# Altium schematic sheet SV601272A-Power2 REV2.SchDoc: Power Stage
size 431 x 279 mm; Date: Not shown in title block; ApprovedBy: Not shown in title block; CheckedBy: Not shown in title block; Author: Not shown in title block; CompanyName: Not shown in title block; Engineer: Not shown in title block; Organization: Not shown in title block; Address1: Not shown in title block; Address2: Not shown in title block; Address3: Not shown in title block; Address4: Not shown in title block; DocumentNumber: 5; Revision: Use project parameter SCH_Rev; SheetNumber: 5; SheetTotal: 11; PageSetup: Record=PageOptions¦CenterHorizontal=True¦CenterVertical=True¦PrintScale=0.62¦XCorrection=1.00¦YCorrection=1.00¦PrintKind=0¦BorderSize=5000000¦LeftOffset=0¦BottomOffset=0¦Orientation=2¦PaperLength=1000¦PaperWidth=1000¦Scale=100¦PaperSource=15¦PrintQuality=600¦MediaType=1¦DitherType=10¦PrintScaleMode=1¦PaperKind=Letter (8.5 x 11")¦PaperIndex=1
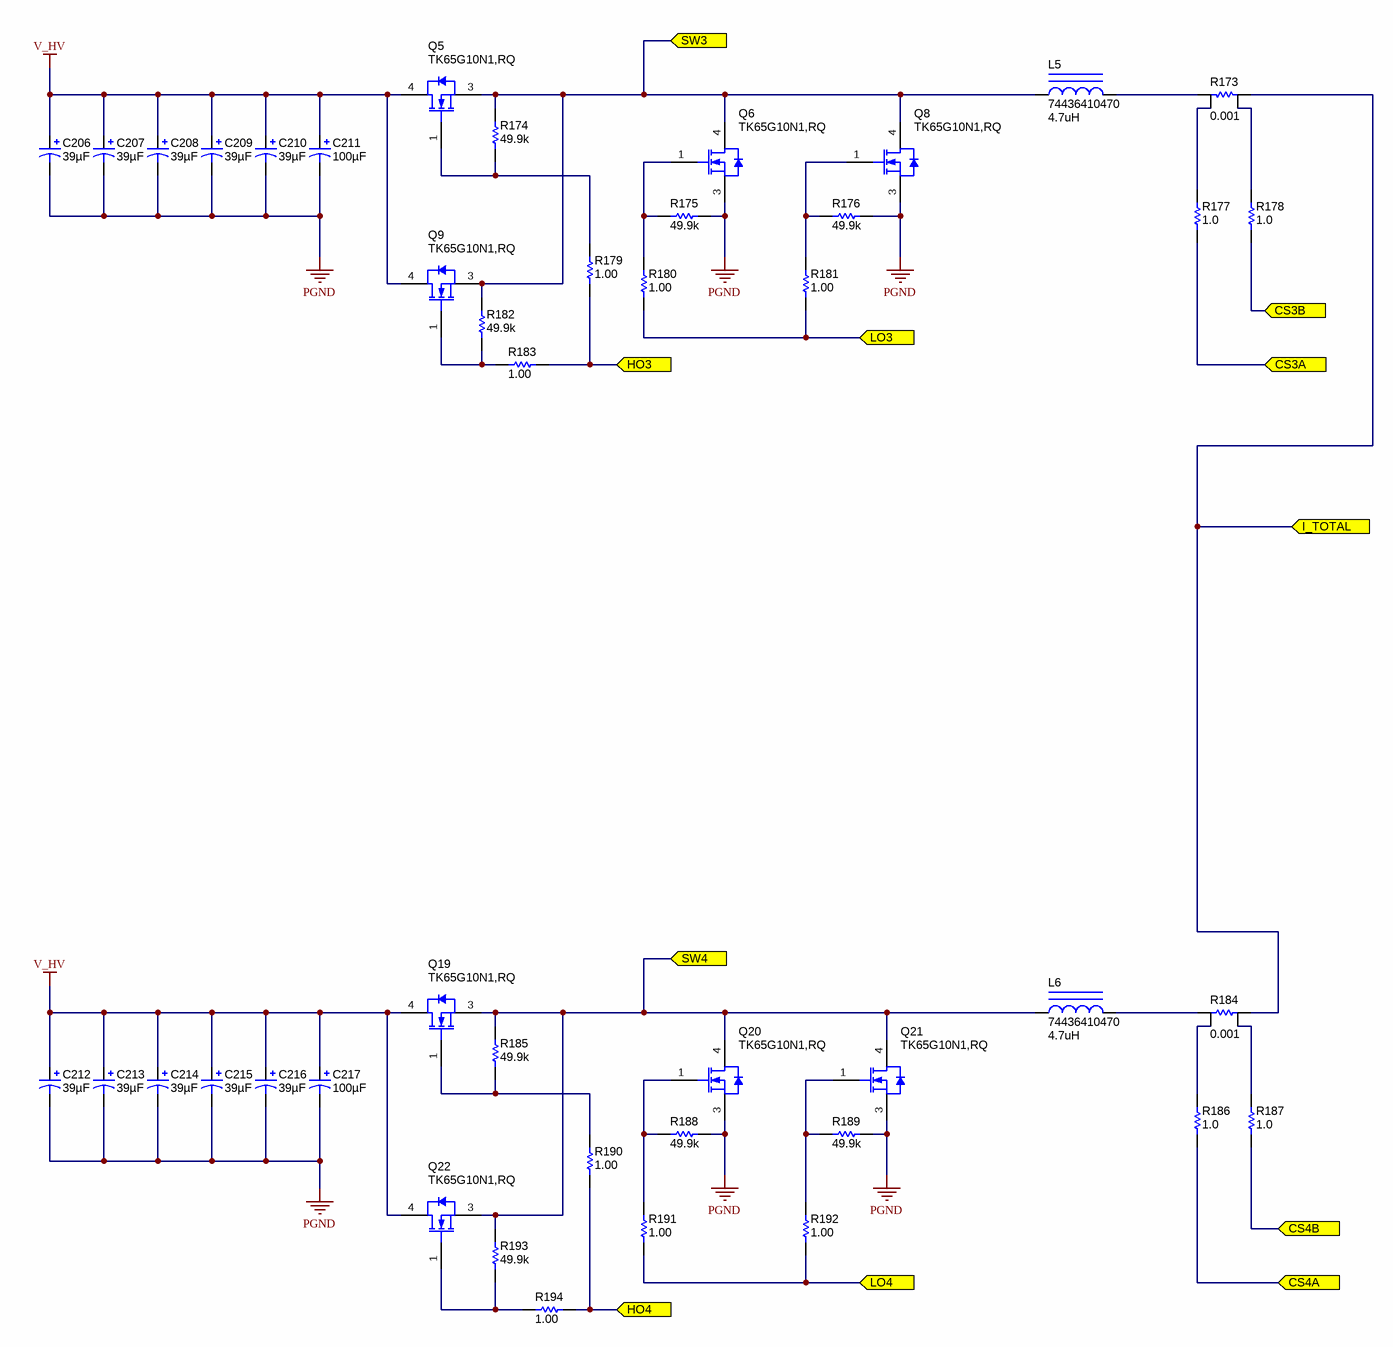
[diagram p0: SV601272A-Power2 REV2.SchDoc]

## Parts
C206  ValueDisplayed: 39µF  [HXA_JA0]  (hidden comment: HHXA800ARA390MJA0G)
C207  ValueDisplayed: 39µF  [HXA_JA0]  (hidden comment: HHXA800ARA390MJA0G)
C208  ValueDisplayed: 39µF  [HXA_JA0]  (hidden comment: HHXA800ARA390MJA0G)
C209  ValueDisplayed: 39µF  [HXA_JA0]  (hidden comment: HHXA800ARA390MJA0G)
C210  ValueDisplayed: 39µF  [HXA_JA0]  (hidden comment: HHXA800ARA390MJA0G)
C211  ValueDisplayed: 100µF  [CAPSMT_62_LH0]  (hidden comment: EMVH101GDA101MLH0S)
C212  ValueDisplayed: 39µF  [HXA_JA0]  (hidden comment: HHXA800ARA390MJA0G)
C213  ValueDisplayed: 39µF  [HXA_JA0]  (hidden comment: HHXA800ARA390MJA0G)
C214  ValueDisplayed: 39µF  [HXA_JA0]  (hidden comment: HHXA800ARA390MJA0G)
C215  ValueDisplayed: 39µF  [HXA_JA0]  (hidden comment: HHXA800ARA390MJA0G)
C216  ValueDisplayed: 39µF  [HXA_JA0]  (hidden comment: HHXA800ARA390MJA0G)
C217  ValueDisplayed: 100µF  [CAPSMT_62_LH0]  (hidden comment: EMVH101GDA101MLH0S)
L5  74436410470  value 4.7uH  [WE-HCF_2818]
L6  74436410470  value 4.7uH  [WE-HCF_2818]
Q5  TK65G10N1,RQ  [DDPAK]
Q6  TK65G10N1,RQ  [DDPAK]
Q8  TK65G10N1,RQ  [DDPAK]
Q9  TK65G10N1,RQ  [DDPAK]
Q19  TK65G10N1,RQ  [DDPAK]
Q20  TK65G10N1,RQ  [DDPAK]
Q21  TK65G10N1,RQ  [DDPAK]
Q22  TK65G10N1,RQ  [DDPAK]
R173  ValueDisplayed: 0.001  [RES_WSL2726]  (hidden comment: WSL27261L000FEB)
R174  ValueDisplayed: 49.9k  [0805_HV]  (hidden comment: CRCW080549K9FKEA)
R175  ValueDisplayed: 49.9k  [0805_HV]  (hidden comment: CRCW080549K9FKEA)
R176  ValueDisplayed: 49.9k  [0805_HV]  (hidden comment: CRCW080549K9FKEA)
R177  ValueDisplayed: 1.0  [0603L]  (hidden comment: CRCW06031R00JNEA)
R178  ValueDisplayed: 1.0  [0603L]  (hidden comment: CRCW06031R00JNEA)
R179  ValueDisplayed: 1.00  [0805_HV]  (hidden comment: CRCW08051R00FKEA)
R180  ValueDisplayed: 1.00  [0805_HV]  (hidden comment: CRCW08051R00FKEA)
R181  ValueDisplayed: 1.00  [0805_HV]  (hidden comment: CRCW08051R00FKEA)
R182  ValueDisplayed: 49.9k  [0805_HV]  (hidden comment: CRCW080549K9FKEA)
R183  ValueDisplayed: 1.00  [0805_HV]  (hidden comment: CRCW08051R00FKEA)
R184  ValueDisplayed: 0.001  [RES_WSL2726]  (hidden comment: WSL27261L000FEB)
R185  ValueDisplayed: 49.9k  [0805_HV]  (hidden comment: CRCW080549K9FKEA)
R186  ValueDisplayed: 1.0  [0603L]  (hidden comment: CRCW06031R00JNEA)
R187  ValueDisplayed: 1.0  [0603L]  (hidden comment: CRCW06031R00JNEA)
R188  ValueDisplayed: 49.9k  [0805_HV]  (hidden comment: CRCW080549K9FKEA)
R189  ValueDisplayed: 49.9k  [0805_HV]  (hidden comment: CRCW080549K9FKEA)
R190  ValueDisplayed: 1.00  [0805_HV]  (hidden comment: CRCW08051R00FKEA)
R191  ValueDisplayed: 1.00  [0805_HV]  (hidden comment: CRCW08051R00FKEA)
R192  ValueDisplayed: 1.00  [0805_HV]  (hidden comment: CRCW08051R00FKEA)
R193  ValueDisplayed: 49.9k  [0805_HV]  (hidden comment: CRCW080549K9FKEA)
R194  ValueDisplayed: 1.00  [0805_HV]  (hidden comment: CRCW08051R00FKEA)

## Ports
CS3A, CS3B, CS4A, CS4B, HO3, HO4, I_TOTAL, LO3, LO4, SW3, SW4

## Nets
PGND: C206.2(-) C207.2(-) C208.2(-) C209.2(-) C210.2(-) C211.2(-) C212.2(-) C213.2(-) C214.2(-) C215.2(-) C216.2(-) C217.2(-) Q6.3(S) Q8.3(S) Q20.3(S) Q21.3(S) R175.2 R176.2 R188.2 R189.2
V_HV: C206.1(+) C207.1(+) C208.1(+) C209.1(+) C210.1(+) C211.1(+) C212.1(+) C213.1(+) C214.1(+) C215.1(+) C216.1(+) C217.1(+) Q5.4(D) Q9.4(D) Q19.4(D) Q22.4(D)
CS3A: R177.1 ; port CS3A
CS3B: R178.1 ; port CS3B
CS4A: R186.1 ; port CS4A
CS4B: R187.1 ; port CS4B
HO3: R179.1 R183.1 ; port HO3
HO4: R190.1 R194.1 ; port HO4
I_TOTAL: R173.2 R184.1 ; port I_TOTAL
LO3: R180.1 R181.1 ; port LO3
LO4: R191.1 R192.1 ; port LO4
SW3: L5.2 Q5.3(S) Q6.4(D) Q8.4(D) Q9.3(S) R174.1 R182.1 ; port SW3
SW4: L6.1 Q19.3(S) Q20.4(D) Q21.4(D) Q22.3(S) R185.2 R193.2 ; port SW4
NetL5_1: L5.1 R173.1
NetL6_2: L6.2 R184.2
NetQ5_1: Q5.1(G) R174.2 R179.2
NetQ6_1: Q6.1(G) R175.1 R180.2
NetQ8_1: Q8.1(G) R176.1 R181.2
NetQ9_1: Q9.1(G) R182.2 R183.2
NetQ19_1: Q19.1(G) R185.1 R190.2
NetQ20_1: Q20.1(G) R188.1 R191.2
NetQ21_1: Q21.1(G) R189.1 R192.2
NetQ22_1: Q22.1(G) R193.1 R194.2
NetR173_3: R173.3 R177.2
NetR173_4: R173.4 R178.2
NetR184_3: R184.3 R187.2
NetR184_4: R184.4 R186.2

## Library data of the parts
C206-C210 C212-C216 = HHXA800ARA390MJA0G: CAP, Aluminum Polymer, 39 µF, 80 V, +/- 20%, 0.035 ohm, AEC-Q200 Grade 1, D10xL10mm SMD; Manufacturer: Chemi-Con; CompType: Capacitor; U/M: EA; ESR_ohm: 0.035; VDC_V: 80; Tolerance_%: 20; Value: 39uF; Polarized: Y; Cap_F: 0.000039; Value2: 80V; IRMS_A: 1.2; TaMin_C: -55; TaMax_C: 125; Cap_Case: 10X10mm; AEC Category: Q200; AEC Grade: 1
C211 C217 = EMVH101GDA101MLH0S: CAP, AL, 100 µF, 100 V, +/- 20%, 0.24 ohm, SMD; Manufacturer: Chemi-Con; Polarized: Y; CompType: Capacitor; Value: 100uF; U/M: EA; Cap_F: 0.0001; Tolerance_%: 20; VDC_V: 100; Value2: 100V; ESR_ohm: 0.24; IRMS_A: 0.65; TaMin_C: -40; TaMax_C: 125; Cap_Case: LH0
L5 L6 = 744364410470: Inductor, 4.7uH, SMT; Manufacturer: WURTH; SymbolCreator: a0413446; U/M: EA
Q5 Q6 Q8 Q9 Q19-Q22 = TK65G10N1,RQ: MOSFET N CH 100V D2PAK; Manufacturer: Toshiba Semiconductor and Storage; SymbolVersion: use current date i.e. 2008-05-20; CompType: Used in some BOM reports.  Useful for finding later.; U/M: EA, IN, or GM; SymbolCreator: Use a-id; Power - Max: 156W; Current - Continuous Drain (Id) @ 25°C: 65A (Ta); FET Type: MOSFET N-Channel, Metal Oxide; FET Feature: Standard; Vgs(th) (Max) @ Id: 4V @ 1mA; Input Capacitance (Ciss) @ Vds: 5400pF @ 50V; Rds On (Max) @ Id, Vgs: 4.5 mOhm @ 32.5A, 10V; Gate Charge (Qg) @ Vgs: 81nC @ 10V
R173 R184 = WSL27261L000FEB: RES, 0.001, 1%, 3 W, 6.6x3x6.9mm; Manufacturer: Vishay-Dale; CompType: Resistor; U/M: EA; Tolerance_%: 1; Value: 0.001; TempCo: 75 ppm/C; Power_W: 3; Value_Code: 1L000; Value2: 3W; EIA_Code: E96; AEC Category: Q200
R174-R176 R182 R185 R188 R189 R193 = CRCW080549K9FKEA: RES, 49.9 k, 1%, 0.125 W, 0805; Manufacturer: Vishay-Dale; CompType: Resistor; Value: 49.9k; Res_ohm: 49900; Value_Code: 49k9; Tolerance_%: 1; Power_W: 0.125; Value2: 0.125W; VDC_V: 150; TempCo: 100 ppm/C; EIA_Code: E96; U/M: EA
R177 R178 R186 R187 = CRCW06031R00JNEA: RES, 1.0, 5%, 0.1 W, 0603; Manufacturer: Vishay-Dale; CompType: Resistor; Value: 1.0; Res_ohm: 1; Value_Code: 1R00; Tolerance_%: 5; Power_W: 0.1; Value2: 0.1W; VDC_V: 75; TempCo: 200 ppm/C; EIA_Code: E24; U/M: EA; AEC Category: Q200
R179-R181 R183 R190-R192 R194 = CRCW08051R00FKEA: RES, 1.00, 1%, 0.125 W, 0805; Manufacturer: Vishay-Dale; CompType: Resistor; Value: 1.00; Res_ohm: 1; Value_Code: 1R00; Power_W: 0.125; Value2: 0.125W; VDC_V: 150; TempCo: 100 ppm/C; EIA_Code: E96; U/M: EA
